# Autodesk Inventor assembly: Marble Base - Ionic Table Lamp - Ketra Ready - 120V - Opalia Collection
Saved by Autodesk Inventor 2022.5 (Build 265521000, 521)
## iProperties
Created: 2025-02
Part Number: Marble Base - Ionic Table Lamp - Ketra Ready - 120V - Opalia Collection
Document SubType Name: Assembly
Designer: AdminForWorker
Title: Marble Base - Ionic Table Lamp - Ketra Ready - 120V - Opalia Collection v32
Author: AdminForWorker
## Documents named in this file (4)
- c:\worker\convert-fusion-r06-cosv3\tmp\job-1\26\temp\files\9f389096-616c-4089-bee7-3010d11b0d58\277928b4-7812-44e9-83b5-e6d9d24e7d58.iam
- c:\worker\convert-fusion-r06-cosv3\tmp\job-1\26\temp\files\9f389096-616c-4089-bee7-3010d11b0d58\Marble Base - Ionic Table Lamp - Ketra Ready - 120V v17.iam
- c:\worker\convert-fusion-r06-cosv3\tmp\job-1\26\temp\files\9f389096-616c-4089-bee7-3010d11b0d58\Ketra - A20 Tunable Lamp v4.iam
- c:\worker\convert-fusion-r06-cosv3\tmp\job-1\26\temp\files\9f389096-616c-4089-bee7-3010d11b0d58\Solitaire Petite (Orb-8.5).ipt
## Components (3 placed, 3 different names)
1. Marble Base - Ionic Table Lamp - Ketra Ready - 120V v17:1 [sub-assembly]
2. Ketra - A20 Tunable Lamp v4:1 [sub-assembly]
3. Solitaire Petite (Orb-8.5):1
